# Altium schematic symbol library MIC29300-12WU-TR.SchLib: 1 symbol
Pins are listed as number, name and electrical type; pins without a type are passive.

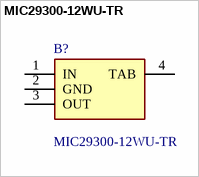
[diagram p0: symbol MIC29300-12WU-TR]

## MIC29300-12WU-TR
designator B?
LDO Voltage Regulators; Manufacturer_Name: Microchip; Geometry.Height: 4.597mm
footprint MIC2930012WUTR
pins: 1 IN, 2 GND, 3 OUT, 4 TAB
